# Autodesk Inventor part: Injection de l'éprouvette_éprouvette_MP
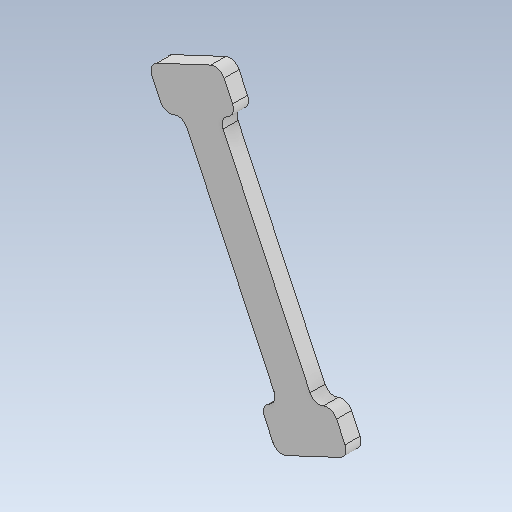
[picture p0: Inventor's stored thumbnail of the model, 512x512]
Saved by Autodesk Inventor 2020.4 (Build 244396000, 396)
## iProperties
Created: 2021-10
Part Number: Injection de l'éprouvette_éprouvette_MP
Material: Générique
Document SubType Name: Modeling
Designer: mel
Density: 1 g/cm^3
Appearance: Par défaut
Author: mel
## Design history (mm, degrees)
derived "éprouvette.ipt"
feature "Solide1::éprouvette.ipt"
tag "FonctionRepérage1"
node "Solide1"
feature "éprouvette.ipt_Corps"
